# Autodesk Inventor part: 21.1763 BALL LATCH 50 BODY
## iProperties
Created: 2007-03
Part Number: 21.1763 BALL LATCH 50 BODY
Document SubType Name: Modeling
Designer: Andy Moles
Material: Steel
Mass: 15.0631 g
Surface Area: 20.9683 cm^2
Volume: 1.91887 cm^3
Density: 7.85 g/cm^3
Author: Andy Moles
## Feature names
1. Extrusion1
2. Extrusion2
3. Extrusion3
4. Chamfer1
5. Chamfer2
